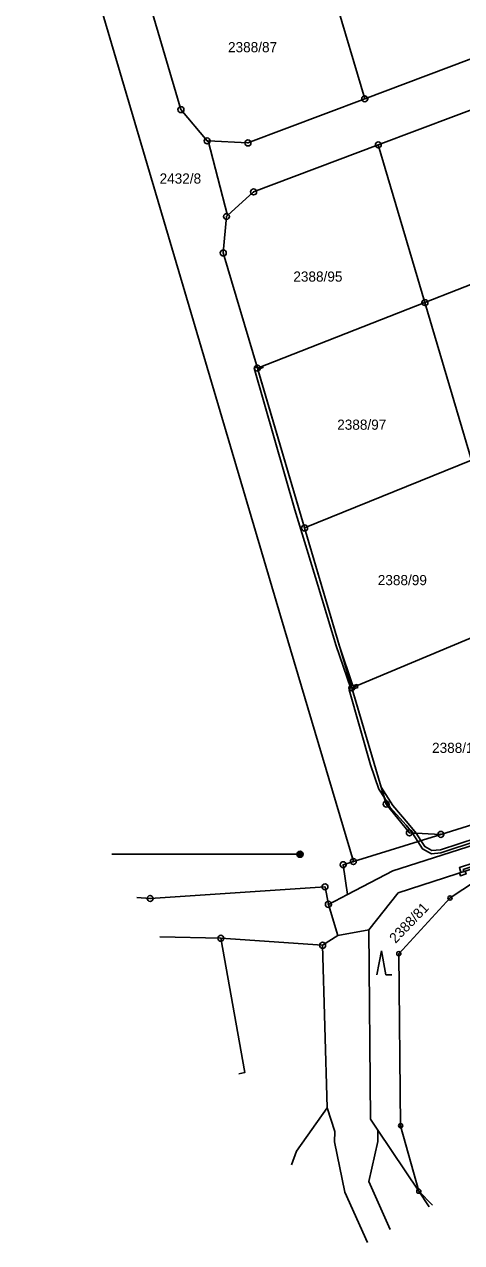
# Model space of a CAD drawing. Extents: x -758836 to -757729, y -1175316 to -1174366.
# Drawn here: x -758630 to -758556.9, y -1175316.1 to -1175112.2 of the extents above; entities that cross this region are included whole.
import ezdxf

# ---------------------------------------------------------------- set-up
doc = ezdxf.new("R2010")
doc.units = 0
for name, color, linetype in [('Hranice parcel', 7, 'Continuous'), ('Parcelní čísla', 7, 'Continuous'), ('Poz předměty', 7, 'Continuous'), ('Věcná břemena k části', 7, 'Continuous'), ('Značky bodu BP', 7, 'Continuous'), ('Značky kultur', 7, 'Continuous')]:
    doc.layers.add(name, color=color, linetype=linetype)

msp = doc.modelspace()

# ---------------------------------------------------------------- linework, layer by layer
at = {"layer": 'Hranice parcel'}
for p, q in [((-758573.07, -1175124.66), (-758581.53, -1175096.02)), ((-758552.21, -1175116.78), (-758573.07, -1175124.66)), ((-758573.07, -1175124.66), (-758592.6, -1175132.04)), ((-758592.6, -1175132.04), (-758599.28, -1175131.71)), ((-758599.28, -1175131.71), (-758596, -1175144.18)), ((-758562.99, -1175158.76), (-758570.79, -1175132.36)), ((-758562.99, -1175158.76), (-758534.96, -1175147.77)), ((-758591.03, -1175169.74), (-758562.99, -1175158.76)), ((-758555.19, -1175185.16), (-758562.99, -1175158.76)), ((-758591.03, -1175169.74), (-758583.12, -1175196.49)), ((-758583.12, -1175196.49), (-758555.19, -1175185.16)), ((-758583.12, -1175196.49), (-758575.22, -1175223.24)), ((-758575.22, -1175223.24), (-758547.39, -1175211.56)), ((-758560.34, -1175247.78), (-758574.97, -1175252.32)), ((-758579.15, -1175259.49), (-758575.95, -1175257.83)), ((-758577.56, -1175264.68), (-758579.15, -1175259.49)), ((-758572.37, -1175263.76), (-758577.56, -1175264.68)), ((-758607.36, -1175264.92), (-758597.14, -1175265.17)), ((-758597.14, -1175265.17), (-758580.11, -1175266.34)), ((-758580.11, -1175266.34), (-758577.56, -1175264.68)), ((-758579.33, -1175293.56), (-758580.11, -1175266.34)), ((-758570.86, -1175297.28), (-758564.02, -1175307.5))]:
    msp.add_line(p, q, dxfattribs=at)
for points in [[(-758574.97, -1175252.32), (-758587.13, -1175211.17), (-758630.01, -1175066.05)], [(-758609.21, -1175108.24), (-758603.81, -1175126.47), (-758599.42, -1175131.7), (-758599.28, -1175131.71)], [(-758570.79, -1175132.36), (-758551.25, -1175124.97), (-758544.44, -1175125.31), (-758540.05, -1175130.54), (-758534.96, -1175147.77)], [(-758596, -1175144.18), (-758591.65, -1175140.24), (-758570.79, -1175132.36)], [(-758596, -1175144.18), (-758596.19, -1175144.35), (-758596.73, -1175150.46), (-758591.03, -1175169.74)], [(-758440.6, -1175188.57), (-758447.78, -1175191.94), (-758489.52, -1175216.53), (-758525.18, -1175238.13), (-758543.6, -1175245.98), (-758568.36, -1175253.9), (-758575.95, -1175257.83)], [(-758575.22, -1175223.24), (-758569.47, -1175242.7), (-758565.59, -1175247.52), (-758560.34, -1175247.78)], [(-758560.34, -1175247.78), (-758544.45, -1175242.84), (-758538.83, -1175240.52)], [(-758572.37, -1175263.76), (-758567.46, -1175257.53), (-758547.85, -1175251.2)], [(-758564.02, -1175307.5), (-758567.06, -1175296.53), (-758567.37, -1175267.75), (-758558.79, -1175258.42), (-758547.85, -1175251.2)], [(-758575.95, -1175257.83), (-758576.67, -1175252.85), (-758574.97, -1175252.32)], [(-758611.17, -1175258.33), (-758608.97, -1175258.5), (-758579.71, -1175256.56), (-758579.15, -1175259.49)], [(-758570.86, -1175297.28), (-758572.09, -1175295.44), (-758572.37, -1175263.76)], [(-758597.14, -1175265.17), (-758593.11, -1175287.61), (-758594.12, -1175287.85)], [(-758585.32, -1175303.09), (-758584.49, -1175300.82), (-758579.33, -1175293.56)], [(-758579.33, -1175293.56), (-758578.06, -1175297.48), (-758578.1, -1175299.22), (-758576.42, -1175307.68), (-758572.6, -1175316.11)], [(-758568.8, -1175313.91), (-758572.38, -1175305.88), (-758570.9, -1175299.18), (-758570.86, -1175297.28)], [(-758562.26, -1175310.13), (-758564.02, -1175307.5)], [(-758564.02, -1175307.5), (-758561.73, -1175309.83)]]:
    msp.add_lwpolyline(points, dxfattribs=at)
at = {"layer": 'Poz předměty'}
msp.add_line((-758583.89, -1175251.11), (-758615.35, -1175251.08), dxfattribs=at)
for radius in [0.5, 0.4, 0.3, 0.2, 0.1]:
    msp.add_circle((-758583.89, -1175251.11), radius, dxfattribs=at)
at = {"layer": 'Věcná břemena k části'}
for points in [[(-758580.9, -1175206.04), (-758577.82, -1175216.22), (-758575.47, -1175223.18), (-758575.66, -1175223.59), (-758572.1, -1175236.14), (-758570.7, -1175240.18), (-758569.77, -1175241.67), (-758570.31, -1175239.85), (-758575.15, -1175223.48), (-758575.22, -1175223.24), (-758574.33, -1175222.87), (-758574.38, -1175222.69), (-758575.03, -1175222.91), (-758577.32, -1175216.12), (-758583.12, -1175196.49), (-758590.96, -1175169.98), (-758590.09, -1175169.64), (-758590.18, -1175169.41), (-758591.03, -1175169.74), (-758591.1, -1175169.5), (-758591.56, -1175169.72), (-758584.74, -1175193.45)], [(-758574.33, -1175222.87), (-758575.22, -1175223.24), (-758575.15, -1175223.48), (-758574.24, -1175223.17)], [(-758565.07, -1175247.55), (-758564.46, -1175247.58), (-758565.77, -1175245.93), (-758568.39, -1175242.96), (-758570.31, -1175239.85), (-758569.77, -1175241.67), (-758568.79, -1175243.26), (-758566.15, -1175246.25)], [(-758556.5, -1175253.99), (-758556.59, -1175253.65), (-758551.86, -1175252.07), (-758552.4, -1175248.79), (-758552.88, -1175248.95), (-758552.42, -1175251.73), (-758557.21, -1175253.33), (-758556.97, -1175254.14), (-758557.22, -1175254.22), (-758557.06, -1175254.7), (-758556.11, -1175254.39), (-758556.27, -1175253.92)]]:
    msp.add_lwpolyline(points, close=True, dxfattribs=at)
msp.add_lwpolyline([(-758554.28, -1175248.35), (-758560.41, -1175250.34), (-758561.82, -1175250.5), (-758563.02, -1175249.82), (-758563.67, -1175248.81), (-758564.46, -1175247.58), (-758565.07, -1175247.55), (-758564.16, -1175248.97), (-758563.38, -1175250.2), (-758561.92, -1175251.02), (-758560.31, -1175250.84), (-758554.1, -1175248.81)], dxfattribs=at)
at = {"layer": 'Značky bodu BP'}
for centre, radius in [((-758573.07, -1175124.66), 0.5), ((-758573.07, -1175124.66), 0.0303), ((-758603.81, -1175126.47), 0.5), ((-758603.81, -1175126.47), 0.0303), ((-758599.42, -1175131.7), 0.5), ((-758599.42, -1175131.7), 0.0303), ((-758592.6, -1175132.04), 0.5), ((-758592.6, -1175132.04), 0.0303), ((-758570.79, -1175132.36), 0.5), ((-758570.79, -1175132.36), 0.0303), ((-758591.65, -1175140.24), 0.5), ((-758591.65, -1175140.24), 0.0303), ((-758596.19, -1175144.35), 0.5), ((-758596.19, -1175144.35), 0.0303), ((-758596.73, -1175150.46), 0.5), ((-758596.73, -1175150.46), 0.0303), ((-758562.99, -1175158.76), 0.5), ((-758562.99, -1175158.76), 0.0303), ((-758591.03, -1175169.74), 0.5), ((-758591.03, -1175169.74), 0.0303), ((-758583.12, -1175196.49), 0.5), ((-758583.12, -1175196.49), 0.0303), ((-758575.22, -1175223.24), 0.5), ((-758575.22, -1175223.24), 0.0303), ((-758569.47, -1175242.7), 0.5), ((-758569.47, -1175242.7), 0.0303), ((-758565.59, -1175247.52), 0.5), ((-758565.59, -1175247.52), 0.0303), ((-758560.34, -1175247.78), 0.5), ((-758560.34, -1175247.78), 0.0303), ((-758574.97, -1175252.32), 0.5), ((-758576.67, -1175252.85), 0.5), ((-758576.67, -1175252.85), 0.0303), ((-758574.97, -1175252.32), 0.0303), ((-758579.71, -1175256.56), 0.5), ((-758608.97, -1175258.5), 0.5), ((-758579.71, -1175256.56), 0.0303), ((-758558.79, -1175258.42), 0.35), ((-758608.97, -1175258.5), 0.0303), ((-758579.15, -1175259.49), 0.5), ((-758579.15, -1175259.49), 0.0303), ((-758558.79, -1175258.42), 0.0212), ((-758597.14, -1175265.17), 0.5), ((-758597.14, -1175265.17), 0.0303), ((-758580.11, -1175266.34), 0.5), ((-758580.11, -1175266.34), 0.0303), ((-758567.37, -1175267.75), 0.35), ((-758567.37, -1175267.75), 0.0212), ((-758567.06, -1175296.53), 0.35), ((-758567.06, -1175296.53), 0.0212), ((-758564.02, -1175307.5), 0.35), ((-758564.02, -1175307.5), 0.0212)]:
    msp.add_circle(centre, radius, dxfattribs=at)
at = {"layer": 'Značky kultur'}
for p, q in [((-758570.27, -1175267.28), (-758571.02, -1175271.28)), ((-758569.52, -1175271.28), (-758570.27, -1175267.28)), ((-758569.52, -1175271.28), (-758568.52, -1175271.28))]:
    msp.add_line(p, q, dxfattribs=at)

# ---------------------------------------------------------------- texts
at = {"layer": 'Parcelní čísla'}
for s, p in [('2388/87', (-758595.94, -1175116.86)), ('2432/8', (-758607.39, -1175138.85)), ('2388/95', (-758585.01, -1175155.26)), ('2388/97', (-758577.67, -1175180.05)), ('2388/99', (-758570.88, -1175206.06)), ('2388/101', (-758561.8, -1175234.14))]:
    msp.add_text(s, height=1.7, dxfattribs=at).set_placement(p)
msp.add_text('2388/81', height=1.7, rotation=46, dxfattribs=at).set_placement((-758567.91, -1175266.11))

doc.saveas('drawing.dxf')
